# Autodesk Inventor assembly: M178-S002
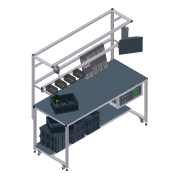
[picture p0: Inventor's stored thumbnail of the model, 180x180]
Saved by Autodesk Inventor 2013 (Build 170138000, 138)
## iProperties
Created: 2006-02
Designer: Autodesk, Inc
Part Number: M178-S002
Description: TEST STATION SERVER SOFTWARE
Engineer: N. GINEER
Author: Autodesk, Inc
Revision Number: A
Part Number: E85-02674
Description: WINDOWS XP PROFESSIONAL, SP2
Part Number: M178-S001
Description: TEST STATION CLIENT SOFTWARE
Created: 2004-11
Part Number: M178-0001
Document SubType Name: Assembly
Designer: Autodesk, Inc.
Manufacturer: Standard
Standards Organization: Custom
Description: TEST STATION, STANDARD
Mass: 86518.4 g
Surface Area: 222281 cm^2
Volume: 49426.1 cm^3
Density: 1.75046 g/cm^3
Author: Autodesk, Inc.
CAGE: 1LJX3
Dept. ID: Product Design
Description #2: ---
Finish #1: ---
Finish #2: ---
Material ID: ---
Project Number: ---
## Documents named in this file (14)
- C:\_ARBEIT\Dropbox\_privat\01_Arbeit\FAQ\inventorfaq.blogspot.com\IVBENCH\_DATEN\Test Station\Test Station.iam
- C:\_ARBEIT\Dropbox\_privat\01_Arbeit\FAQ\inventorfaq.blogspot.com\IVBENCH\_DATEN\Test Station\Components\M178-1000.iam
- C:\_ARBEIT\Dropbox\_privat\01_Arbeit\FAQ\inventorfaq.blogspot.com\IVBENCH\_DATEN\Test Station\Components\M178-2000.iam
- C:\_ARBEIT\Dropbox\_privat\01_Arbeit\FAQ\inventorfaq.blogspot.com\IVBENCH\_DATEN\Test Station\Components\Standard Tote.iam
- C:\_ARBEIT\Dropbox\_privat\01_Arbeit\FAQ\inventorfaq.blogspot.com\IVBENCH\_DATEN\Test Station\Components\22-128Z2 Hardware Set.iam
- C:\_ARBEIT\Dropbox\_privat\01_Arbeit\FAQ\inventorfaq.blogspot.com\IVBENCH\_DATEN\Test Station\Components\Filled Tote 2.iam
- C:\_ARBEIT\Dropbox\_privat\01_Arbeit\FAQ\inventorfaq.blogspot.com\IVBENCH\_DATEN\Test Station\Components\22-124.ipt
- C:\_ARBEIT\Dropbox\_privat\01_Arbeit\FAQ\inventorfaq.blogspot.com\IVBENCH\_DATEN\Test Station\Components\M178-3000.iam
- C:\_ARBEIT\Dropbox\_privat\01_Arbeit\FAQ\inventorfaq.blogspot.com\IVBENCH\_DATEN\Test Station\Components\M178-4000 Phantom.iam
- C:\_ARBEIT\Dropbox\_privat\01_Arbeit\FAQ\inventorfaq.blogspot.com\IVBENCH\_DATEN\Test Station\Components\PC, RACK MOUNT, 2U.ipt
- C:\_ARBEIT\Dropbox\_privat\01_Arbeit\FAQ\inventorfaq.blogspot.com\IVBENCH\_DATEN\Test Station\Components\Monitor Phantom.iam
- C:\_ARBEIT\Dropbox\_privat\01_Arbeit\FAQ\inventorfaq.blogspot.com\IVBENCH\_DATEN\Test Station\Components\50-601.ipt
- C:\Program Files\Autodesk\Inventor 2009\Samples\Models\Assemblies\Test Station\Content\22-1x Part Bins.ipt
- C:\Program Files\Autodesk\Inventor 2009\Samples\Models\Assemblies\Test Station\Content\50-60x Zero Gravity Tool Balancer.ipt
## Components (28 placed, 14 different names)
1. M178-1000:1 [sub-assembly] — Mate:1, Flush:1, Mate:2, Mate:3, Mate:10, Flush:2, Flush:3, Mate:11
2. M178-2000:1 [sub-assembly] — Mate:1, Flush:1, Mate:2, Mate:21, Mate:22, Mate:23
3. M178-3000:1 [sub-assembly] — Mate:10, Flush:2, Flush:3, Mate:12, Mate:13, Angle:1, Angle:2, Mate:18, Mate:19, Flush:5, Mate:20, Flush:6
4. Standard Tote:14 [sub-assembly] — Mate:4
5. Filled Tote 2:1 [sub-assembly] — Mate:11
6. 50-601:1 — Angle:2
7. Monitor Phantom:1 [sub-assembly] — Mate:18, Mate:19, Flush:5
8. M178-4000 Phantom:1 [sub-assembly] — Mate:20, Flush:6
9. PC, RACK MOUNT, 2U:1 — Mate:21, Mate:22, Mate:23, Flush:7, Flush:8, Mate:24
10. PC, RACK MOUNT, 2U:2 — Flush:7, Flush:8, Mate:24
11. Windows XP Professional, SP2:1
12. Windows XP Professional, SP2:2
13. Test Station Client Software:1
14. Test Station Server Software:1
15. Standard Tote:6 [sub-assembly] — Mate:3
16. Standard Tote:7 [sub-assembly] — Mate:4
17. Standard Tote:8 [sub-assembly]
18. Standard Tote:9 [sub-assembly]
19. Standard Tote:10 [sub-assembly]
20. Standard Tote:11 [sub-assembly]
21. 22-124:1 — Mate:14, Mate:15, Flush:4
22. 22-128Z2 Hardware Set:1 [sub-assembly] — Mate:12, Mate:13, Angle:1, Mate:14, Mate:15, Flush:4
23. 22-124:2
24. 22-128Z2 Hardware Set:4 [sub-assembly]
25. 22-124:3
26. 22-128Z2 Hardware Set:5 [sub-assembly]
27. 22-124:4
28. 22-128Z2 Hardware Set:6 [sub-assembly]
## Component patterns: Totes Pattern (6 elements)
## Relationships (27: Mate 17, Flush 8, Angle 2)
- Mate:1: M178-1000:1 ↔ M178-2000:1
- Flush:1: M178-1000:1 ↔ M178-2000:1
- Mate:2: M178-1000:1 ↔ M178-2000:1
- Mate:3: M178-1000:1 ↔ Standard Tote:6
- Mate:4: Standard Tote:14 ↔ Standard Tote:7
- Mate:10: M178-1000:1 ↔ M178-3000:1
- Flush:2: M178-1000:1 ↔ M178-3000:1
- Flush:3: M178-1000:1 ↔ M178-3000:1
- Mate:11: M178-1000:1 ↔ Filled Tote 2:1
- Mate:12: M178-3000:1 ↔ 22-128Z2 Hardware Set:1
- Mate:13: M178-3000:1 ↔ 22-128Z2 Hardware Set:1
- Angle:1: M178-3000:1 ↔ 22-128Z2 Hardware Set:1
- Mate:14: 22-124:1 ↔ 22-128Z2 Hardware Set:1
- Mate:15: 22-124:1 ↔ 22-128Z2 Hardware Set:1
- Flush:4: 22-124:1 ↔ 22-128Z2 Hardware Set:1
- Angle:2: M178-3000:1 ↔ 50-601:1
- Mate:18: M178-3000:1 ↔ Monitor Phantom:1
- Mate:19: M178-3000:1 ↔ Monitor Phantom:1
- Flush:5: M178-3000:1 ↔ Monitor Phantom:1
- Mate:20: M178-3000:1 ↔ M178-4000 Phantom:1
- Flush:6: M178-3000:1 ↔ M178-4000 Phantom:1
- Mate:21: M178-2000:1 ↔ PC, RACK MOUNT, 2U:1
- Mate:22: M178-2000:1 ↔ PC, RACK MOUNT, 2U:1
- Mate:23: M178-2000:1 ↔ PC, RACK MOUNT, 2U:1
- Flush:7: PC, RACK MOUNT, 2U:1 ↔ PC, RACK MOUNT, 2U:2
- Flush:8: PC, RACK MOUNT, 2U:1 ↔ PC, RACK MOUNT, 2U:2
- Mate:24: PC, RACK MOUNT, 2U:1 ↔ PC, RACK MOUNT, 2U:2
